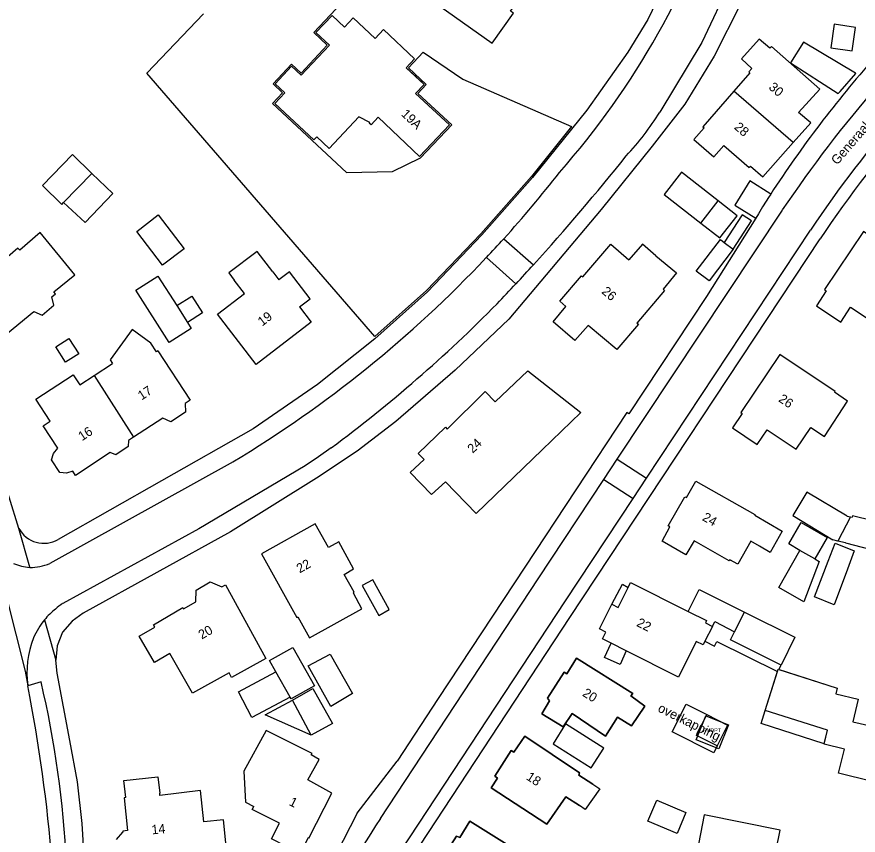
# Model space of a CAD drawing. Extents: x 194485 to 197793, y 468269 to 470822.
# Drawn here: x 194552.2 to 194661, y 470202.3 to 470308 of the extents above; entities that cross this region are included whole.
import ezdxf

# ---------------------------------------------------------------- set-up
doc = ezdxf.new("R2010")
doc.units = 0
for name, color, linetype in [('BAG plantopografie panden grensvlak pand', 7, 'Continuous'), ('BAG plantopografie panden kenmerkpunt', 7, 'Continuous'), ('BAG plantopografie panden lijnelement overig', 7, 'Continuous'), ('BAG plantopografie panden tekst opmerking', 7, 'Continuous'), ('BGT grensvlak gebouwinstallatie plus 1', 7, 'Continuous'), ('BGT grensvlak overig bouwwerk uitbreiding populatie', 7, 'Continuous'), ('BGT grensvlak pand op maaiveld', 7, 'Continuous'), ('BGT grensvlak pand op maaiveld LR', 7, 'Continuous'), ('BGT grensvlak wegdeel', 7, 'Continuous'), ('BGT tekst huisnummerreeks', 7, 'Continuous'), ('BGT tekst openbare ruimte label weg', 7, 'Continuous'), ('GEM grensvlak beperking gebied', 7, 'Continuous'), ('GEM grensvlak beperking object', 7, 'Continuous')]:
    doc.layers.add(name, color=color, linetype=linetype)

msp = doc.modelspace()

# ---------------------------------------------------------------- linework, layer by layer
at = {"layer": 'BAG plantopografie panden grensvlak pand'}
for points in [[(194642.77, 470213.84), (194640.08, 470215.17), (194641.42, 470217.86)], [(194641.42, 470217.86), (194644.1, 470216.52), (194642.77, 470213.84)]]:
    msp.add_lwpolyline(points, dxfattribs=at)
at = {"layer": 'BAG plantopografie panden lijnelement overig'}
msp.add_lwpolyline([(194642.77, 470213.84), (194642.32, 470212.94), (194636.95, 470215.62), (194638.74, 470219.2), (194641.42, 470217.86)], dxfattribs=at)
at = {"layer": 'BGT grensvlak gebouwinstallatie plus 1'}
for p, q in [((194561.95, 470287.77), (194564.65, 470285.16)), ((194564.65, 470285.16), (194561.06, 470281.45)), ((194561.06, 470281.45), (194558.28, 470284.02)), ((194645.34, 470282.29), (194642.87, 470284.21)), ((194643.11, 470279.44), (194645.34, 470282.29)), ((194640.64, 470281.36), (194643.11, 470279.44)), ((194640.05, 470275.14), (194643.18, 470279.24)), ((194643.18, 470279.24), (194643.67, 470278.86)), ((194644.83, 470277.98), (194641.7, 470273.88)), ((194641.7, 470273.88), (194640.05, 470275.14)), ((194629.12, 470232.13), (194630.5, 470234.7)), ((194630.5, 470234.7), (194631.24, 470234.3)), ((194642.13, 470229.26), (194642.44, 470229.88)), ((194642.44, 470229.88), (194645, 470228.54)), ((194642.72, 470227.31), (194650.53, 470223.42)), ((194650.73, 470223.68), (194651.02, 470224.26)), ((194580.9, 470220.82), (194585.73, 470223.39)), ((194582.62, 470217.51), (194580.9, 470220.82)), ((194587.57, 470220.13), (194582.62, 470217.51)), ((194584.35, 470217.82), (194587.86, 470219.73)), ((194590.3, 470215.22), (194584.35, 470217.82)), ((194623.17, 470216.66), (194621.54, 470214.08)), ((194628.09, 470213.55), (194623.17, 470216.66)), ((194621.54, 470214.08), (194626.46, 470210.97)), ((194626.46, 470210.97), (194628.09, 470213.55))]:
    msp.add_line(p, q, dxfattribs=at)
for points in [[(194572.9, 470270.7), (194574.84, 470271.93), (194576.22, 470269.75), (194574.29, 470268.52)], [(194653.96, 470232.44), (194650.72, 470234.28), (194653.45, 470239.07)], [(194655.35, 470237.97), (194655.93, 470237.64), (194653.96, 470232.44)], [(194638.99, 470231.19), (194640.41, 470234.03), (194646.28, 470231.1)], [(194641.17, 470227.33), (194642.42, 470226.7), (194642.72, 470227.31)], [(194656.59, 470214.1), (194648.42, 470216.73), (194648.94, 470218.4)]]:
    msp.add_lwpolyline(points, dxfattribs=at)
at = {"layer": 'BGT grensvlak overig bouwwerk uitbreiding populatie'}
for p, q in [((194645.96, 470282.43), (194643.67, 470278.86)), ((194644.83, 470277.98), (194647.17, 470281.65)), ((194647.17, 470281.65), (194645.96, 470282.43)), ((194643.67, 470278.86), (194644.83, 470277.98)), ((194557.28, 470265.36), (194558.97, 470266.43)), ((194558.97, 470266.43), (194560.24, 470264.45)), ((194558.54, 470263.37), (194557.28, 470265.36)), ((194560.24, 470264.45), (194558.54, 470263.37)), ((194598.23, 470235.29), (194596.87, 470234.53)), ((194600.37, 470231.42), (194598.23, 470235.29)), ((194596.87, 470234.53), (194599.01, 470230.67)), ((194599.01, 470230.67), (194600.37, 470231.42)), ((194628.2, 470225.22), (194629.03, 470227.08)), ((194631, 470226.1), (194630.21, 470224.33)), ((194630.21, 470224.33), (194628.2, 470225.22)), ((194640.04, 470214.61), (194641.29, 470217.72)), ((194641.29, 470217.72), (194644.2, 470216.55)), ((194644.2, 470216.55), (194642.95, 470213.45)), ((194642.95, 470213.45), (194640.04, 470214.61)), ((194633.79, 470204.09), (194634.95, 470206.83)), ((194634.95, 470206.83), (194638.72, 470205.23)), ((194638.72, 470205.23), (194637.56, 470202.49)), ((194637.56, 470202.49), (194633.79, 470204.09))]:
    msp.add_line(p, q, dxfattribs=at)
msp.add_lwpolyline([(194657.43, 470304.01), (194660.18, 470303.6), (194660.62, 470306.62), (194657.87, 470307.03), (194657.43, 470304.01)], dxfattribs=at)
at = {"layer": 'BGT grensvlak pand op maaiveld'}
for p, q in [((194603.83, 470300.23), (194602.57, 470301.42)), ((194558.28, 470284.02), (194561.95, 470287.77)), ((194640.64, 470281.36), (194642.87, 470284.21)), ((194585.31, 470275.04), (194586.1, 470274.01)), ((194572.9, 470270.7), (194574.29, 470268.52)), ((194562.22, 470261.67), (194564.6, 470263.22)), ((194659.57, 470243.48), (194659.99, 470243.4)), ((194659.99, 470243.4), (194660.18, 470243.37)), ((194658.36, 470240.28), (194657.69, 470240.43)), ((194659.32, 470240.06), (194658.36, 470240.28)), ((194655.35, 470237.97), (194653.45, 470239.07)), ((194645, 470228.54), (194646.28, 470231.1)), ((194642.13, 470229.26), (194641.17, 470227.33)), ((194644.49, 470227.52), (194645, 470228.54)), ((194651.02, 470224.26), (194644.49, 470227.52)), ((194631, 470226.1), (194629.03, 470227.08)), ((194587.57, 470220.13), (194585.73, 470223.39)), ((194648.94, 470218.4), (194650.53, 470223.42)), ((194590.3, 470215.22), (194587.86, 470219.73)), ((194656.99, 470215.85), (194648.94, 470218.4)), ((194593.02, 470216.71), (194590.3, 470215.22)), ((194656.59, 470214.1), (194656.99, 470215.85)), ((194566.31, 470207.15), (194566.09, 470209.36)), ((194566.31, 470207.15), (194566.11, 470207.12)), ((194565.13, 470201.73), (194565.95, 470202.7))]:
    msp.add_line(p, q, dxfattribs=at)
for points in [[(194606.02, 470310), (194613.69, 470304.58), (194616.45, 470308.45), (194616.05, 470308.73), (194619.09, 470313), (194611.82, 470318.14), (194606.02, 470310)], [(194594.57, 470306.67), (194592.98, 470308.17), (194590.9, 470305.96), (194592.63, 470304.34), (194588.99, 470300.45)], [(194594.57, 470306.67), (194595.69, 470307.86), (194598.54, 470305.2), (194599.61, 470306.34), (194603.65, 470302.56), (194602.57, 470301.42)], [(194652.59, 470291.75), (194654.84, 470294.29), (194653.28, 470295.64), (194656.02, 470298.64), (194649.75, 470304.16), (194649.56, 470303.95), (194648.18, 470305.13), (194645.88, 470302.56), (194647.21, 470301.34), (194646.83, 470300.9), (194646.96, 470300.78), (194644.9, 470298.4)], [(194660.63, 470300.7), (194653.91, 470304.73), (194652.23, 470302.04), (194658.39, 470298.08), (194658.63, 470298.36)], [(194588.99, 470300.45), (194587.76, 470301.6), (194585.63, 470299.34), (194586.86, 470298.18)], [(194603.76, 470298.07), (194604.88, 470299.26), (194603.83, 470300.23)], [(194658.63, 470298.36), (194660.66, 470300.68), (194660.63, 470300.7)], [(194591.01, 470292.49), (194590.63, 470292.09), (194585.58, 470296.82), (194586.86, 470298.18)], [(194603.76, 470298.07), (194608.17, 470294.03), (194604.28, 470289.94), (194598.94, 470295.02), (194598.02, 470294.05), (194597.79, 470294.27), (194597.86, 470294.34), (194596.46, 470295.06)], [(194644.9, 470298.4), (194640.9, 470293.78), (194641.06, 470293.64), (194639.74, 470292.13), (194642.3, 470289.89), (194643.62, 470291.39), (194646.88, 470288.52), (194647.05, 470288.72), (194648.67, 470287.33), (194652.59, 470291.75)], [(194591.01, 470292.49), (194592.62, 470290.97), (194596.46, 470295.06)], [(194561.95, 470287.77), (194559.45, 470290.22), (194555.54, 470286.21)], [(194642.87, 470284.21), (194638.13, 470287.91), (194635.91, 470285.06), (194640.64, 470281.36)], [(194555.54, 470286.21), (194558.04, 470283.77), (194558.28, 470284.02)], [(194649.67, 470285.1), (194646.96, 470286.79), (194645.02, 470283.67), (194647.73, 470281.98)], [(194649.67, 470285.1), (194649.37, 470284.64), (194649.07, 470284.17), (194648.62, 470283.44), (194648.07, 470282.55), (194647.73, 470281.98)], [(194567.74, 470280.27), (194570.51, 470282.4), (194573.85, 470278.03), (194571.08, 470275.91), (194567.74, 470280.27)], [(194549.82, 470267.14), (194550.3, 470266.55), (194554.46, 470269.95), (194555.5, 470269.47), (194557.04, 470270.73), (194556.78, 470271.84), (194557.24, 470272.22), (194557.04, 470272.47), (194559.75, 470274.69), (194555.26, 470280.13), (194552.61, 470277.85), (194552.39, 470278.1), (194545.63, 470272.31), (194547.76, 470269.68)], [(194669.03, 470271.91), (194670.52, 470274.13), (194668.7, 470275.35), (194668.83, 470275.5), (194661.66, 470280.28), (194656.6, 470272.76), (194656.85, 470272.62), (194655.57, 470270.68), (194658.73, 470268.56), (194659.98, 470270.49), (194663.68, 470268.02)], [(194634.83, 470277.11), (194637.49, 470274.92), (194635.76, 470272.8), (194635.95, 470272.66), (194632.35, 470268.43), (194632.58, 470268.28), (194629.8, 470265.01), (194626.08, 470268.12), (194624.37, 470266.17), (194621.56, 470268.59), (194623.2, 470270.57), (194622.43, 470271.26), (194625.2, 470274.54), (194625.37, 470274.4), (194629.01, 470278.63), (194631.35, 470276.61)], [(194634.83, 470277.11), (194633.08, 470278.64), (194631.35, 470276.61)], [(194585.31, 470275.04), (194583.32, 470277.7), (194579.64, 470274.93), (194580.33, 470273.98)], [(194588.77, 470270.53), (194590.13, 470271.56), (194587.47, 470275.04), (194586.1, 470274.01)], [(194567.61, 470272.7), (194570.48, 470274.5), (194572.9, 470270.7)], [(194588.77, 470270.53), (194590.28, 470268.55), (194583.17, 470263.1), (194578.19, 470269.58), (194581.66, 470272.24), (194580.33, 470273.98)], [(194574.29, 470268.52), (194574.78, 470267.75), (194571.92, 470265.93), (194567.61, 470272.7)], [(194570.48, 470264.85), (194570.29, 470264.73), (194569.57, 470265.84), (194567.15, 470267.61), (194564.29, 470263.69), (194564.6, 470263.22)], [(194570.48, 470264.85), (194574.64, 470258.48), (194574.01, 470258.07), (194574.05, 470256.93), (194572.13, 470255.67), (194571.1, 470256.16), (194567.32, 470253.68)], [(194647.9, 470252.75), (194649.21, 470254.63), (194652.96, 470252.16), (194654.86, 470254.97), (194656.64, 470253.79), (194659.6, 470258.33), (194657.93, 470259.5), (194657.98, 470259.58), (194650.85, 470264.36), (194645.82, 470256.88), (194645.98, 470256.76), (194644.72, 470254.91), (194647.9, 470252.75)], [(194614.07, 470258.25), (194618.26, 470262.28), (194625.11, 470256.88), (194620.13, 470252.07)], [(194567.32, 470253.68), (194566.67, 470253.25), (194566.65, 470252.48), (194565.02, 470251.41), (194564.31, 470251.7), (194559.84, 470248.77), (194559.49, 470249.3), (194558.65, 470249.04), (194557.81, 470249.15), (194556.74, 470250.78), (194556.98, 470251.6), (194557.54, 470252.28), (194555.64, 470255.17), (194556.56, 470255.78), (194554.71, 470258.61), (194559.52, 470261.76), (194560.37, 470260.46), (194562.22, 470261.67)], [(194603.09, 470249.15), (194604.87, 470250.81), (194604.13, 470251.6), (194607.65, 470255), (194607.84, 470254.73), (194612.76, 470259.58), (194614.07, 470258.25)], [(194620.13, 470252.07), (194620.13, 470252.07), (194611.61, 470243.85), (194607.66, 470247.94), (194605.82, 470246.3), (194603.09, 470249.15)], [(194645.44, 470237.28), (194644.38, 470237.85), (194644.29, 470237.71), (194639.77, 470240.32), (194638.71, 470238.49), (194635.64, 470240.27), (194636.65, 470242.11), (194636.4, 470242.23), (194638.56, 470245.99), (194638.78, 470245.89), (194639.99, 470248.03), (194647.63, 470243.71), (194647.61, 470243.61), (194651.14, 470241.57), (194649.58, 470238.82), (194648.23, 470239.63)], [(194659.57, 470243.48), (194654.35, 470246.6), (194652.54, 470243.58), (194657.69, 470240.43)], [(194659.32, 470240.06), (194664.65, 470238.68), (194665.49, 470242.26), (194660.23, 470243.55), (194660.18, 470243.37)], [(194596.82, 470231.54), (194595.73, 470233.54), (194595.83, 470233.67), (194594.53, 470235.98), (194595.77, 470236.68), (194593.85, 470240.17), (194592.5, 470239.44), (194590.81, 470242.49), (194583.86, 470238.61), (194588.43, 470230.42), (194588.57, 470230.51), (194590.06, 470227.8), (194596.82, 470231.54)], [(194653.45, 470239.07), (194651.99, 470239.91), (194653.59, 470242.67)], [(194653.59, 470242.67), (194656.95, 470240.74), (194655.35, 470237.97)], [(194648.23, 470239.63), (194647.08, 470240.27), (194645.44, 470237.28)], [(194657.08, 470237.67), (194658, 470239.99), (194660.47, 470239.02), (194659.59, 470236.65)], [(194659.59, 470236.65), (194657.85, 470232.04), (194655.31, 470233.08), (194657.08, 470237.67)], [(194575.37, 470232.42), (194575.4, 470233.94), (194577.22, 470235), (194578.73, 470234.36)], [(194631.24, 470234.3), (194631.55, 470234.91), (194638.99, 470231.19)], [(194578.73, 470234.36), (194579.21, 470234.63), (194584.42, 470225.13), (194579.98, 470222.64), (194579.68, 470223.28), (194574.93, 470220.62), (194572.03, 470225.77), (194570.02, 470224.6), (194568.07, 470228.01), (194570.06, 470229.16), (194569.92, 470229.47), (194573.71, 470231.68), (194573.79, 470231.51), (194575.37, 470232.42)], [(194629.12, 470232.13), (194629.95, 470231.71), (194631.24, 470234.3)], [(194629.03, 470227.08), (194627.91, 470227.64), (194628.34, 470228.53), (194627.53, 470228.93), (194629.12, 470232.13)], [(194638.99, 470231.19), (194641.38, 470230), (194641.24, 470229.7), (194642.13, 470229.26)], [(194646.28, 470231.1), (194652.8, 470227.85), (194651.02, 470224.26)], [(194641.17, 470227.33), (194640.94, 470226.88), (194640.05, 470227.32), (194637.74, 470222.72), (194631, 470226.1)], [(194585.73, 470223.39), (194584.9, 470224.85), (194587.9, 470226.54)], [(194587.9, 470226.54), (194590.7, 470221.6), (194587.7, 470219.91), (194587.57, 470220.13)], [(194595.63, 470220.58), (194592.82, 470218.91), (194589.89, 470224.15), (194592.72, 470225.67), (194595.63, 470220.58)], [(194628.32, 470215.07), (194629.87, 470217.54), (194631.69, 470216.4), (194633.38, 470218.97), (194631.61, 470220.28), (194631.85, 470220.58), (194624.59, 470225.17), (194623.31, 470223.13), (194622.97, 470223.36), (194620.83, 470220), (194621.06, 470219.66), (194620.07, 470217.98), (194622.84, 470216.28), (194624.01, 470217.99), (194628.32, 470215.07)], [(194650.53, 470223.42), (194650.63, 470223.72), (194650.73, 470223.68)], [(194650.73, 470223.68), (194658.24, 470221.28), (194658.08, 470220.56)], [(194587.86, 470219.73), (194590.49, 470221.24), (194593.02, 470216.71)], [(194658.08, 470220.56), (194660.98, 470219.87), (194660.29, 470216.95), (194668.58, 470215.05), (194667.96, 470212.52), (194668.26, 470212.48), (194669.25, 470211.23), (194668.76, 470209.05), (194667.39, 470208.23), (194666.76, 470208.37), (194666.17, 470205.95), (194662.23, 470206.87), (194662.79, 470209.22), (194658.43, 470210.29), (194659.19, 470213.41), (194656.58, 470214.04), (194656.59, 470214.1)], [(194589.83, 470209.44), (194591.31, 470212.07), (194590.27, 470212.65), (194590.39, 470212.84), (194584.47, 470215.82), (194581.57, 470210.58), (194581.8, 470206.56), (194582.85, 470205.98)], [(194626.68, 470208.88), (194624.86, 470210.04), (194624.97, 470210.33), (194617.88, 470215.08), (194616.46, 470213.02), (194616.14, 470213.23), (194614.01, 470209.92), (194614.36, 470209.66), (194613.54, 470208.41), (194620.73, 470203.71), (194623.18, 470207.26), (194624.94, 470206.12)], [(194566.09, 470209.36), (194570.48, 470209.83), (194570.71, 470207.7)], [(194589.98, 470201.89), (194592.93, 470207.73), (194589.83, 470209.44)], [(194626.68, 470208.88), (194627.6, 470208.27), (194625.71, 470205.6), (194624.94, 470206.12)], [(194566.44, 470198.54), (194566.45, 470198.41), (194576.86, 470199.51), (194576.83, 470200.17), (194579.36, 470200.45), (194578.94, 470204.27), (194576.39, 470204), (194576, 470208.07), (194570.72, 470207.43), (194570.71, 470207.7)], [(194566.11, 470207.12), (194566.53, 470202.91), (194565.93, 470202.83), (194565.95, 470202.7)], [(194586.17, 470203.83), (194582.65, 470205.62), (194582.85, 470205.98)], [(194649.91, 470198.06), (194650.89, 470202.96), (194641.09, 470204.93), (194640.11, 470200.03), (194649.91, 470198.06)], [(194589.98, 470201.89), (194589.89, 470201.93), (194588.88, 470199.93), (194585.16, 470201.83), (194586.17, 470203.83)], [(194616.43, 470192.99), (194619.78, 470198.09), (194617.97, 470199.3), (194618.04, 470199.57), (194610.78, 470204.11), (194609.5, 470201.97), (194609.07, 470202.17), (194606.99, 470198.92), (194607.42, 470198.69), (194606.32, 470197.03), (194609.11, 470195.22), (194610.16, 470197), (194616.43, 470192.99)]]:
    msp.add_lwpolyline(points, dxfattribs=at)
at = {"layer": 'BGT grensvlak pand op maaiveld LR'}
for p, q in [((194652.59, 470291.75), (194644.9, 470298.4)), ((194562.22, 470261.67), (194567.32, 470253.68)), ((194659.99, 470243.4), (194658.36, 470240.28))]:
    msp.add_line(p, q, dxfattribs=at)
at = {"layer": 'BGT grensvlak wegdeel'}
for p, q in [((194629.84, 470250.84), (194651.18, 470283.04)), ((194633.62, 470248.41), (194654.81, 470280.44)), ((194615.18, 470279.34), (194619.01, 470275.97)), ((194616.75, 470273.51), (194612.92, 470276.89)), ((194580.18, 470250.53), (194556.49, 470237.4)), ((194628.11, 470248.22), (194629.84, 470250.84)), ((194629.84, 470250.84), (194633.62, 470248.41)), ((194628.11, 470248.22), (194631.89, 470245.79)), ((194631.89, 470245.79), (194633.62, 470248.41)), ((194553.91, 470236.89), (194552.5, 470241.9)), ((194548.98, 470240.56), (194553.3, 470223.49)), ((194555.82, 470230.1), (194557.27, 470224.91)), ((194553.3, 470223.49), (194553.66, 470221.6)), ((194555.38, 470222.1), (194553.66, 470221.6)), ((194596.21, 470205.13), (194601.39, 470211.86))]:
    msp.add_line(p, q, dxfattribs=at)
for points in [[(194652.17, 470394.39), (194652.08, 470392.68), (194650.44, 470374.25), (194648.52, 470358.98), (194645.74, 470342.38), (194644.16, 470334.39), (194642.06, 470326.53), (194639.25, 470319.29), (194635.98, 470312.25), (194633.79, 470307.66), (194631.22, 470303.41), (194625.9, 470295.95), (194618.89, 470287.25), (194612.33, 470279.83), (194605.32, 470272.49), (194598.5, 470266.42), (194591.11, 470260.49), (194582.77, 470254.79), (194570.96, 470248.08), (194557.57, 470240.49)], [(194660.33, 470375.79), (194658.56, 470358.39), (194655.14, 470338.34), (194652.9, 470329.51), (194649.24, 470318.16), (194645.77, 470309.63), (194642.37, 470302.92), (194638.58, 470296.72), (194634.36, 470291.3), (194627.75, 470283.1), (194615.84, 470268.95), (194608.91, 470262.36), (194601.23, 470255.74), (194596.24, 470251.91), (194590.99, 470248.4), (194579.87, 470241.48), (194560.8, 470230.95), (194559.41, 470229.93), (194558.16, 470228.5), (194557.47, 470226.75), (194557.27, 470224.91)], [(194552.5, 470241.9), (194549.98, 470250), (194545.77, 470258.98), (194544.42, 470261.5), (194540.37, 470267.9), (194538.06, 470271.19), (194528.56, 470283.04), (194521.79, 470289.95), (194515.24, 470296.12), (194508.37, 470301.96), (194493.23, 470312.72), (194490.75, 470314.36)], [(194644.5, 470312.66), (194640.75, 470304.66), (194635.33, 470295.69)], [(194647.73, 470281.98), (194641.38, 470271.86), (194631.33, 470256.72), (194631.09, 470256.88), (194617.88, 470236.89), (194606.71, 470219.95), (194601.39, 470211.86)], [(194564.02, 470127.14), (194569.02, 470136.22), (194587.65, 470171.11), (194597.89, 470190.27), (194600.72, 470195.34), (194603.36, 470199.49), (194623.7, 470230.41), (194656.05, 470279.32)], [(194592.87, 470252.32), (194591.21, 470251.15), (194589.52, 470250), (194575.75, 470241.88), (194558.17, 470232.22)], [(194599.22, 470204.44), (194619.61, 470235.39), (194628.11, 470248.22)], [(194601.91, 470200.3), (194623.13, 470232.54), (194631.89, 470245.79)], [(194556.64, 470134.94), (194558.93, 470149.49), (194560.24, 470159.7), (194561.1, 470172.15), (194561.43, 470182.43), (194561.18, 470195.9), (194560.67, 470203.81), (194560.07, 470209.18), (194559.11, 470214.54), (194557.44, 470223.23), (194557.27, 470224.91)], [(194596.21, 470205.13), (194591.74, 470196.4), (194580.17, 470175), (194566.1, 470148.6), (194558.59, 470134.32)]]:
    msp.add_lwpolyline(points, dxfattribs=at)
for centre, radius, start, end in [((194543.72, 470357.32), 104.9, 318.5603, 342.618), ((194777.05, 470202.09), 152.04, 138.6225, 146.9085), ((194784.85, 470193.18), 161.08, 138.8579, 146.0892), ((194607.82, 470312.3), 32.13, 316.176, 328.8785), ((194781.8, 470195.45), 152.81, 138.8648, 146.2065), ((194781.05, 470196.12), 150.15, 138.5732, 146.3486), ((194404.41, 470470.94), 289.94, 317.7429, 321.4004), ((194501.05, 470382.4), 153.78, 317.9152, 322.0783), ((194507.26, 470376.66), 145.32, 316.6414, 317.9553), ((194500.84, 470382.57), 154.04, 300.9993, 316.6805), ((194395.98, 470478.65), 301.37, 317.103, 317.7367), ((194262.71, 470604.38), 484.58, 316.5188, 316.9374), ((194482.91, 470400.66), 184.65, 306.5476, 315.3692), ((194555.72, 470243.65), 3.66, 208.5302, 300.4344), ((194554.16, 470242.35), 5.47, 244.7396, 267.3951), ((194554.16, 470242.35), 5.47, 267.4253, 295.2714), ((194563.06, 470224.09), 9.42, 128.1455, 140.3116), ((194565.05, 470222.53), 11.89, 125.4156, 131.0637), ((194563.02, 470224.11), 9.37, 140.2477, 156.9132), ((194565.8, 470223.29), 12.25, 158.4631, 187.9054), ((194430.31, 470192.58), 128.5, 2.7074, 13.2783), ((194356.49, 470182.89), 200.93, 4.5118, 11.1085), ((194754.84, 470103.09), 185.71, 146.925, 152.5321)]:
    msp.add_arc(centre, radius, start, end, dxfattribs=at)
at = {"layer": 'GEM grensvlak beperking gebied'}
for points in [[(194595.64, 470311.31), (194590.62, 470305.95), (194592.35, 470304.33), (194588.98, 470300.73), (194587.75, 470301.88), (194585.35, 470299.33), (194586.58, 470298.17), (194585.3, 470296.81), (194594.83, 470287.88), (194600.79, 470288), (194604.4, 470289.78), (194608.46, 470294.04), (194604.05, 470298.08), (194605.16, 470299.27), (194602.85, 470301.42), (194604.75, 470303.45), (194609.86, 470299.96), (194623.92, 470293.81), (194618.74, 470287.38), (194612.19, 470279.97), (194605.18, 470272.64), (194598.52, 470266.71), (194569.04, 470300.72)], [(194569.04, 470300.72), (194576.37, 470308.39)]]:
    msp.add_lwpolyline(points, dxfattribs=at)
at = {"layer": 'GEM grensvlak beperking object'}
for points in [[(194585.58, 470296.82), (194586.86, 470298.18), (194585.63, 470299.34), (194587.76, 470301.6), (194588.99, 470300.45), (194592.63, 470304.34), (194590.9, 470305.96), (194592.98, 470308.17), (194594.57, 470306.67), (194595.69, 470307.86), (194598.54, 470305.2), (194599.61, 470306.34), (194603.65, 470302.56), (194602.57, 470301.42), (194604.88, 470299.26), (194603.76, 470298.07), (194608.17, 470294.03), (194604.28, 470289.94), (194598.94, 470295.02), (194598.02, 470294.05), (194597.79, 470294.27), (194597.86, 470294.34), (194596.46, 470295.06), (194592.62, 470290.97), (194591.01, 470292.49), (194590.63, 470292.09), (194585.58, 470296.82)], [(194620.07, 470217.98), (194621.06, 470219.66), (194620.83, 470220), (194622.97, 470223.36), (194623.31, 470223.13), (194624.59, 470225.17), (194631.85, 470220.58), (194631.61, 470220.28), (194633.38, 470218.97), (194631.69, 470216.4), (194629.87, 470217.54), (194628.32, 470215.07), (194624.01, 470217.99), (194622.84, 470216.28), (194620.07, 470217.98)], [(194648.94, 470218.4), (194650.63, 470223.72), (194658.24, 470221.28), (194658.08, 470220.56), (194660.98, 470219.87), (194660.29, 470216.95), (194668.58, 470215.05), (194667.96, 470212.52), (194668.26, 470212.48), (194669.25, 470211.23), (194668.76, 470209.05), (194667.39, 470208.23), (194666.76, 470208.37), (194666.17, 470205.95), (194662.23, 470206.87), (194662.79, 470209.22), (194658.43, 470210.29), (194659.19, 470213.41), (194656.58, 470214.04), (194656.99, 470215.85), (194648.94, 470218.4)], [(194613.54, 470208.41), (194614.36, 470209.66), (194614.01, 470209.92), (194616.14, 470213.23), (194616.46, 470213.02), (194617.88, 470215.08), (194624.97, 470210.33), (194624.86, 470210.04), (194626.68, 470208.88), (194627.6, 470208.27), (194625.71, 470205.6), (194624.94, 470206.12), (194623.18, 470207.26), (194620.73, 470203.71), (194613.54, 470208.41)], [(194606.32, 470197.03), (194607.42, 470198.69), (194606.99, 470198.92), (194609.07, 470202.17), (194609.5, 470201.97), (194610.78, 470204.11), (194618.04, 470199.57), (194617.97, 470199.3), (194619.78, 470198.09), (194616.43, 470192.99), (194610.16, 470197), (194609.11, 470195.22), (194606.32, 470197.03)]]:
    msp.add_lwpolyline(points, dxfattribs=at)

# ---------------------------------------------------------------- texts
at = {"layer": 'BAG plantopografie panden kenmerkpunt'}
msp.add_text('PNDPT', height=0.5, dxfattribs=at).set_placement((194640.91, 470215.6))
at = {"layer": 'BAG plantopografie panden tekst opmerking'}
msp.add_text('overkapping', height=1.2, rotation=333.4862, dxfattribs=at).set_placement((194634.98, 470218.32))
at = {"layer": 'BGT tekst huisnummerreeks'}
for s, rotation, p in [('30', 319.2, (194649.32, 470298.76)), ('19A', 316.4, (194601.83, 470295.33)), ('28', 319.1, (194644.86, 470293.61)), ('26', 319.3, (194627.73, 470272.38)), ('19', 37.5, (194583.95, 470267.98)), ('17', 33.3, (194568.37, 470258.43)), ('26', 326.1, (194650.58, 470258.38)), ('16', 33.2, (194560.67, 470253.17)), ('24', 44.6, (194611.17, 470251.55)), ('24', 330.6, (194640.73, 470243.02)), ('22', 29.2, (194588.8, 470236.1)), ('20', 30, (194576.14, 470227.55)), ('22', 333.4, (194632.24, 470229.35)), ('20', 327.9, (194625.24, 470220.35)), ('18', 327, (194617.98, 470209.55)), ('1', 333.2, (194587.33, 470206.22)), ('14', 5.7, (194569.71, 470202.39))]:
    msp.add_text(s, height=1.2, rotation=rotation, dxfattribs=at).set_placement(p)
at = {"layer": 'BGT tekst openbare ruimte label weg'}
msp.add_text('Generaal Van der Heydenlaan', height=1.2, rotation=49.1, dxfattribs=at).set_placement((194658.26, 470288.79))

doc.saveas('drawing.dxf')
